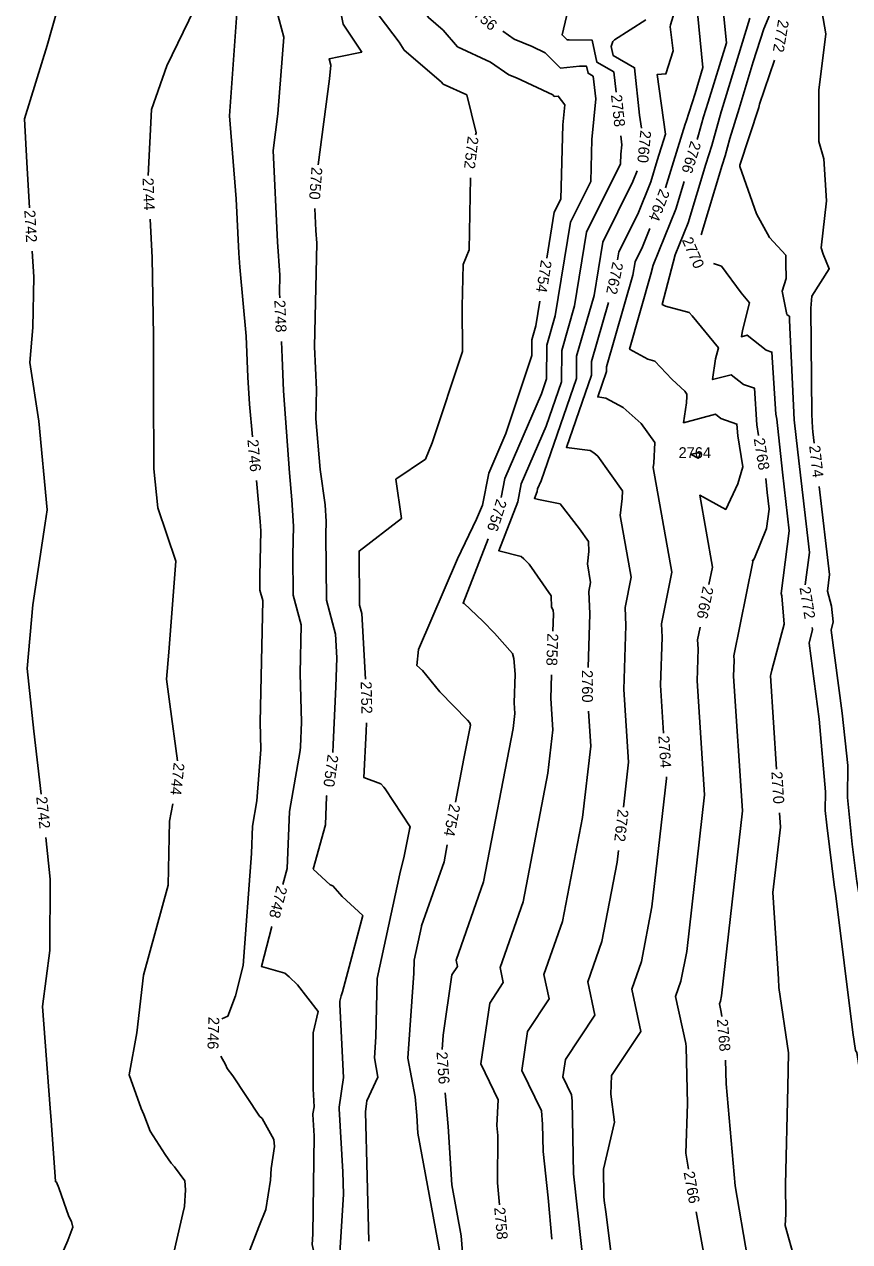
# Model space of a CAD drawing. Extents: x 1326424 to 1329294, y 1001359 to 1003823.
# Drawn here: x 1328128 to 1328279.2, y 1001910 to 1002132.9 of the extents above; entities that cross this region are included whole.
import ezdxf

# ---------------------------------------------------------------- set-up
doc = ezdxf.new("R2010")
doc.units = 0
doc.layers.add('Prop Rem of Exist Asph Pvmt', color=7, linetype='Continuous')
doc.layers.add('Scratch_Level_3', color=7, linetype='Continuous')

msp = doc.modelspace()

# ---------------------------------------------------------------- linework, layer by layer
at = {"layer": 'Prop Rem of Exist Asph Pvmt'}
for points in [[(1328241.88, 1002133.77), (1328236.13, 1002130.1), (1328235.87, 1002129.8), (1328235.55, 1002128.91), (1328235.92, 1002127.24), (1328239.82, 1002125.01), (1328240.76, 1002116.3), (1328241.1, 1002113.91)], [(1328240.33, 1002106.15), (1328239.53, 1002104.16), (1328233.99, 1002093.08), (1328232.41, 1002083.27), (1328229.22, 1002072.21), (1328229.17, 1002068.11), (1328222.69, 1002049.33), (1328222.06, 1002047.86), (1328221.97, 1002047.39), (1328221.48, 1002046.14), (1328222.26, 1002045.95), (1328226.19, 1002045.13), (1328229.74, 1002040.55), (1328231.36, 1002038.22), (1328231.44, 1002036.42), (1328231.19, 1002034.14), (1328231.78, 1002030.76), (1328231.45, 1002029.09), (1328231.66, 1002025.01), (1328231.32, 1002015.14)], [(1328231.37, 1002007.15), (1328231.79, 1002000.78), (1328230.3, 1001987.69), (1328226.62, 1001968.64), (1328223.22, 1001958.93), (1328224.17, 1001954.48), (1328220.22, 1001948.54), (1328219.2, 1001941.39), (1328222.77, 1001934.01), (1328222.99, 1001931.56), (1328223.09, 1001926.51), (1328224.02, 1001918.04), (1328224.69, 1001910.46)]]:
    msp.add_lwpolyline(points, dxfattribs=at)
at = {"layer": 'Scratch_Level_3'}
for points in [[(1328174.09, 1002197.45), (1328174.05, 1002197.26), (1328172.89, 1002195.7), (1328170.57, 1002179.75), (1328170.43, 1002179.18), (1328170.61, 1002178.82), (1328170.68, 1002176.08), (1328170.29, 1002175.71), (1328170.1, 1002175.19), (1328169.74, 1002172.85), (1328164.96, 1002162.58), (1328165.4, 1002155.7), (1328164.24, 1002155.43), (1328161.5, 1002155.85), (1328160.64, 1002149.86), (1328160.24, 1002146.37), (1328159.14, 1002135.67), (1328154.16, 1002125.34), (1328151.31, 1002117.38), (1328150.69, 1002105.26)], [(1328186.52, 1002193.49), (1328185.24, 1002190.14), (1328184.63, 1002189.33), (1328184.32, 1002187.2), (1328182.95, 1002181.36), (1328184.28, 1002178.62), (1328186.74, 1002177.48), (1328183.91, 1002176.94), (1328181.55, 1002174.66), (1328180.02, 1002170.39), (1328179.07, 1002164.22), (1328179.67, 1002160.72), (1328180.72, 1002158.47), (1328179.89, 1002156.68), (1328182.68, 1002146.2), (1328183.84, 1002141.66), (1328185.42, 1002138.19), (1328186.47, 1002132.95), (1328189.85, 1002127.87), (1328185.66, 1002127), (1328183.85, 1002126.65), (1328184.16, 1002125.5), (1328183.96, 1002122.96), (1328181.89, 1002107.19)], [(1328161.06, 1002192.1), (1328159.57, 1002188.92), (1328155.58, 1002182.38), (1328154.2, 1002178.24), (1328153.03, 1002176.74), (1328147.39, 1002166.79), (1328144.91, 1002161.62), (1328140.75, 1002153.04), (1328137.03, 1002143.45), (1328135.1, 1002139.25), (1328132.19, 1002129.06), (1328128.05, 1002115.64), (1328128.5, 1002107.62), (1328128.99, 1002099.36)], [(1328259.04, 1002190.58), (1328258.85, 1002190.19), (1328258.41, 1002185.32), (1328258.53, 1002183.16), (1328258.56, 1002181.96), (1328258.98, 1002175.15), (1328259.79, 1002170.02), (1328260.62, 1002167.82), (1328261.57, 1002164.95), (1328263.57, 1002159.93), (1328265.56, 1002154.79), (1328266.9, 1002151.53), (1328265.77, 1002146.24), (1328265.47, 1002145.5), (1328265.8, 1002144.97), (1328265.97, 1002142.2), (1328264.63, 1002134.73), (1328263.54, 1002132.12), (1328261.58, 1002126.07), (1328258.97, 1002117.54), (1328257.31, 1002112.07), (1328256.4, 1002108.84), (1328255.87, 1002107.16), (1328252.02, 1002094.39)], [(1328229.92, 1002177.59), (1328235.12, 1002172.38), (1328238.26, 1002166.48), (1328239.25, 1002160.72), (1328239.29, 1002158.49), (1328239.55, 1002149.92), (1328241.22, 1002143.6), (1328244.07, 1002140.8), (1328244.85, 1002140.01), (1328245.22, 1002140.03), (1328248.36, 1002140.12), (1328247.82, 1002137.48), (1328246.4, 1002132.83), (1328246.33, 1002132.48), (1328246.92, 1002128.11), (1328245.58, 1002123.88), (1328243.96, 1002123.75), (1328245.51, 1002112.86), (1328243.97, 1002107.99), (1328242.8, 1002104.1), (1328240.41, 1002098.18), (1328236.95, 1002091.26), (1328236.72, 1002089.81)], [(1328176.84, 1002172.32), (1328176.72, 1002171.99), (1328174.72, 1002159), (1328174.75, 1002158.83), (1328174.8, 1002158.72), (1328174.76, 1002158.63), (1328179.34, 1002141.41), (1328179.76, 1002139.78), (1328180.32, 1002138.53), (1328180.99, 1002135.23), (1328174.81, 1002137.15), (1328173.88, 1002136.97), (1328175.6, 1002130.61), (1328174.48, 1002116.58), (1328173.6, 1002109.83), (1328174.39, 1002093.12), (1328174.85, 1002087), (1328174.78, 1002083.72), (1328174.81, 1002082.89)], [(1328199.24, 1002167.33), (1328201.03, 1002160.94), (1328201.9, 1002157.4), (1328204.62, 1002151.23), (1328206.55, 1002145.44), (1328200.31, 1002140.84), (1328197.72, 1002140.5), (1328199.08, 1002138.79), (1328199.71, 1002137.96), (1328202.05, 1002134.19), (1328204.74, 1002131.89), (1328207.39, 1002128.8), (1328213.43, 1002126.04), (1328216.79, 1002123.71), (1328218.2, 1002123.13), (1328224.85, 1002120.01), (1328225.11, 1002119.75), (1328225.86, 1002119.82), (1328227.06, 1002118.23), (1328226.71, 1002114.53), (1328226.32, 1002100.93), (1328225.13, 1002098.55), (1328223.76, 1002090.12)], [(1328276.46, 1002153.66), (1328276.39, 1002153.61), (1328274.88, 1002152.89), (1328274.77, 1002151.74), (1328274.75, 1002151.25), (1328274.22, 1002144.85), (1328274.13, 1002135.42), (1328274.86, 1002131.18), (1328273.56, 1002120.88), (1328273.56, 1002120.81), (1328273.62, 1002113.84), (1328273.62, 1002111.51), (1328274.51, 1002108.33), (1328275.02, 1002100.61), (1328274, 1002092), (1328274.37, 1002090.84), (1328275.51, 1002088.18), (1328272.31, 1002083.2), (1328272.11, 1002080.99), (1328272.32, 1002061.5), (1328272.44, 1002059.04), (1328272.51, 1002058.34), (1328272.75, 1002056.28)], [(1328172.17, 1002148.36), (1328173.66, 1002143.28), (1328169.36, 1002145.31), (1328167.26, 1002144.98), (1328166.99, 1002135.91), (1328167.04, 1002135.73), (1328166.98, 1002134.99), (1328165.64, 1002116.2), (1328166.86, 1002101), (1328167.33, 1002091.06), (1328167.52, 1002088.5), (1328168.68, 1002075.86), (1328168.95, 1002068.36), (1328169.31, 1002063.37), (1328169.85, 1002057.38)], [(1328229.18, 1002142.2), (1328226.55, 1002131.01), (1328227.47, 1002130.09), (1328227.82, 1002130.13), (1328232.06, 1002130.06), (1328232.94, 1002126.01), (1328236.05, 1002124.23), (1328236.45, 1002120.51)], [(1328190.52, 1002137.86), (1328196.71, 1002129.69), (1328197.62, 1002128.23), (1328204.41, 1002122.41), (1328204.77, 1002121.99), (1328209.07, 1002120.02), (1328210.79, 1002113.06), (1328210.71, 1002112.74)], [(1328256.05, 1002135.58), (1328256.65, 1002129.54), (1328253.34, 1002118.69), (1328252.49, 1002116.04), (1328251.55, 1002112.71), (1328251.27, 1002111.83)], [(1328260.95, 1002134.06), (1328255.76, 1002117.08), (1328255.71, 1002116.91), (1328253.97, 1002110.77), (1328252.89, 1002107.37), (1328249.66, 1002096.61), (1328247.29, 1002090.75), (1328245.58, 1002084.21), (1328244.86, 1002081.67), (1328245.49, 1002081.32), (1328249.81, 1002080.15), (1328250.38, 1002079.56), (1328255.19, 1002073.69), (1328254.68, 1002071.71), (1328254.11, 1002067.88), (1328257.54, 1002068.79), (1328259.8, 1002067.01), (1328261.79, 1002066.33), (1328262.22, 1002059.6), (1328262.55, 1002057.65)], [(1328251.35, 1002135.04), (1328252.35, 1002125.02), (1328250.91, 1002120.31), (1328249.27, 1002115.17), (1328249.12, 1002114.64), (1328246.94, 1002107.79), (1328245.51, 1002103.03)], [(1328215.72, 1002131.67), (1328217.79, 1002130.23), (1328221.05, 1002128.89), (1328223.46, 1002127.76), (1328226.29, 1002124.92), (1328229.73, 1002125.28), (1328231.04, 1002125.26), (1328231.31, 1002124), (1328232.27, 1002123.45), (1328232.72, 1002119.32), (1328232.02, 1002111.84), (1328231.79, 1002104.16), (1328228.08, 1002096.73), (1328225.3, 1002079.56), (1328223.76, 1002074.19), (1328223.69, 1002068.01), (1328222.78, 1002065.29), (1328216.09, 1002049.77), (1328215.42, 1002046.3)], [(1328265.45, 1002126.36), (1328262.75, 1002118.3), (1328262.62, 1002117.73), (1328259.12, 1002107.15), (1328259.13, 1002106.89), (1328262.15, 1002098.25), (1328264.54, 1002093.91), (1328267.54, 1002090.69), (1328267.55, 1002089.29), (1328267.58, 1002086.43), (1328266.9, 1002084.08), (1328267.75, 1002079.82), (1328268.14, 1002079.52), (1328268.2, 1002079.5), (1328268.24, 1002078.76), (1328269.08, 1002060.5), (1328269.72, 1002054.63), (1328271.87, 1002036.2), (1328271.11, 1002030.32)], [(1328237.3, 1002112.56), (1328237.48, 1002110.88), (1328237.32, 1002109.15), (1328237.27, 1002107.38), (1328231.04, 1002094.91), (1328228.85, 1002081.42), (1328226.49, 1002073.2), (1328226.42, 1002067.48), (1328223.62, 1002059.35), (1328219.08, 1002048.81), (1328218.43, 1002045.51), (1328214.95, 1002036.55), (1328219.08, 1002035.51), (1328219.55, 1002035.07), (1328220.5, 1002034.09), (1328224.52, 1002028.3), (1328224.62, 1002026.23), (1328224.92, 1002025.69), (1328224.98, 1002024.94), (1328224.87, 1002021.84)], [(1328209.77, 1002104.84), (1328209.52, 1002091.68), (1328208.43, 1002088.94), (1328208.25, 1002081.25), (1328208.3, 1002073.02), (1328202.74, 1002056.29), (1328201.55, 1002053.35), (1328196.09, 1002049.64), (1328197.11, 1002042.45), (1328189.37, 1002036.49), (1328189.46, 1002026.6), (1328189.87, 1002025.07), (1328190.52, 1002013.04)], [(1328248.9, 1002104.19), (1328247.37, 1002099.11), (1328243.23, 1002088.86), (1328242.8, 1002087.22), (1328238.91, 1002073.48), (1328242.28, 1002071.61), (1328243.53, 1002071.27), (1328246.66, 1002067.99), (1328247.5, 1002067.15), (1328249.03, 1002065.79), (1328249.43, 1002065.23), (1328249.38, 1002064.22), (1328249.37, 1002064.2), (1328249.35, 1002063.65), (1328248.81, 1002060), (1328254.63, 1002061.55), (1328255.63, 1002060.76), (1328258.58, 1002059.75), (1328258.72, 1002057.61), (1328259.67, 1002051.93), (1328258.75, 1002048.78), (1328256.54, 1002044.12), (1328251.76, 1002046.71), (1328254.08, 1002033.57), (1328253.43, 1002030.38)], [(1328151.06, 1002097.27), (1328151.46, 1002090.24), (1328151.68, 1002075.93), (1328151.7, 1002066.17), (1328151.76, 1002051.55), (1328152.47, 1002044.4), (1328155.8, 1002034.65), (1328154.49, 1002017.98), (1328154.08, 1002013.02), (1328154.68, 1002008.43), (1328156.1, 1001998.08)], [(1328181.26, 1002099.24), (1328181.46, 1002095.18), (1328181.63, 1002092.86), (1328181.2, 1002073.9), (1328181.54, 1002066.05), (1328181.44, 1002060.72), (1328182.21, 1002051.4), (1328183.12, 1002044.98), (1328183.31, 1002041.89), (1328183.25, 1002039.53), (1328183.36, 1002027.52), (1328185.05, 1002021.27), (1328185.29, 1002016.93), (1328185.07, 1002011.61), (1328184.6, 1002001.05), (1328184.52, 1001999.61)], [(1328242.64, 1002095.57), (1328241.29, 1002092.21), (1328239.91, 1002089.44), (1328239.51, 1002086.99), (1328234.68, 1002070.23), (1328234.67, 1002069.36), (1328233.07, 1002064.71), (1328234.59, 1002064.51), (1328237.77, 1002062.76), (1328241.05, 1002059.84), (1328243.54, 1002056.38), (1328243.35, 1002052.59), (1328243.26, 1002051.82), (1328246.64, 1002032.63), (1328244.74, 1002023.19), (1328244.87, 1002020.74), (1328244.57, 1002011.93), (1328245.15, 1002003.14)], [(1328129.47, 1002091.38), (1328129.74, 1002086.73), (1328129.59, 1002077.41), (1328129.06, 1002071.01), (1328130.67, 1002060.25), (1328132.22, 1002044.06), (1328131.85, 1002041.62), (1328129.6, 1002026.67), (1328128.55, 1002014.97), (1328129.75, 1002003.49), (1328131.13, 1001991.99)], [(1328254.31, 1002089.18), (1328255.73, 1002088.67), (1328259.37, 1002083.79), (1328260.89, 1002081.94), (1328259.59, 1002076.91), (1328259.42, 1002075.75), (1328260.46, 1002076.03), (1328263.97, 1002073.26), (1328264.99, 1002072.92), (1328265.72, 1002061.58), (1328265.88, 1002060.62), (1328266.93, 1002050.93), (1328268.18, 1002040.19), (1328266.69, 1002028.71), (1328266.8, 1002028.32), (1328267.23, 1002023.11), (1328265, 1002014.71), (1328264.77, 1002013.86), (1328264.73, 1002013.63), (1328265.86, 1001996.55)], [(1328222.48, 1002082.23), (1328221.75, 1002077.71), (1328221.02, 1002075.18), (1328220.99, 1002072.28), (1328216.25, 1002058.03), (1328213.11, 1002050.73), (1328211.97, 1002044.88), (1328210.86, 1002042.34), (1328207.42, 1002035.07), (1328200.22, 1002018.44), (1328199.94, 1002015.56), (1328200.98, 1002014.6), (1328204.13, 1002010.71), (1328209.21, 1002005.53), (1328209.65, 1002005.03), (1328209.77, 1002004.63), (1328208.57, 1001998.5), (1328207.03, 1001990.52)], [(1328235.06, 1002082), (1328231.95, 1002071.22), (1328231.92, 1002068.73), (1328227.34, 1002055.46), (1328231.68, 1002054.89), (1328232.37, 1002054.51), (1328233.07, 1002053.88), (1328237.65, 1002047.52), (1328237.58, 1002046.13), (1328237.22, 1002042.98), (1328239.21, 1002031.69), (1328238.09, 1002026.14), (1328238.26, 1002022.88), (1328237.87, 1002011.12), (1328238.74, 1001997.82), (1328237.81, 1001989.61)], [(1328175.15, 1002074.89), (1328175.28, 1002071.92), (1328175.5, 1002065.82), (1328176.59, 1002050.82), (1328177.03, 1002045.87), (1328177.33, 1002041.04), (1328177.2, 1002035.75), (1328177.27, 1002028.44), (1328178.75, 1002022.99), (1328178.55, 1002014.06), (1328178.81, 1002005.16), (1328178.61, 1002000.66), (1328178.57, 1001999.97), (1328176.61, 1001988.82), (1328176.19, 1001978.36), (1328175.4, 1001975.46)], [(1328251.46, 1002054.51), (1328250.24, 1002054.21), (1328250.18, 1002054.2), (1328251.51, 1002053.48), (1328251.65, 1002053.76), (1328251.83, 1002054.38), (1328251.46, 1002054.51)], [(1328170.56, 1002049.41), (1328171.24, 1002041.89), (1328171.35, 1002040.18), (1328171.15, 1002031.97), (1328171.18, 1002029.36), (1328171.71, 1002027.41), (1328171.22, 1002005.16), (1328171.36, 1002000.18), (1328170.64, 1001990.76), (1328169.82, 1001986.1), (1328169.62, 1001981.13), (1328168.15, 1001960.58), (1328166.73, 1001955.06), (1328165.29, 1001951.3), (1328164.23, 1001950.81)], [(1328263.86, 1002049.75), (1328264.14, 1002047.23), (1328264.49, 1002044.18), (1328264.03, 1002040.6), (1328261.78, 1002035.22), (1328261.57, 1002034.77), (1328261.45, 1002034.84), (1328261.51, 1002034.5), (1328258.03, 1002017.28), (1328258.08, 1002016.48), (1328257.98, 1002013.56), (1328259.61, 1001988.92), (1328255.74, 1001955.03), (1328255.56, 1001954.07), (1328255.39, 1001953.58), (1328255.71, 1001952.07), (1328255.8, 1001951.24)], [(1328273.68, 1002048.34), (1328275.57, 1002032.21), (1328275.17, 1002029.17), (1328275.91, 1002026.39), (1328276.23, 1002023.51), (1328275.86, 1002022), (1328277.89, 1002006.78), (1328278.91, 1001997.2), (1328278.85, 1001991.36), (1328279.7, 1001982.81), (1328280.56, 1001975.97), (1328281.23, 1001972.09), (1328282.01, 1001965.89), (1328284.21, 1001949.16)], [(1328212.99, 1002038.71), (1328208.41, 1002026.95), (1328208.62, 1002026.9), (1328212.04, 1002023.67), (1328214.18, 1002021.47), (1328217.45, 1002017.73), (1328217.72, 1002016.84), (1328217.93, 1002013.97), (1328217.75, 1002008.68), (1328217.88, 1002006.72), (1328217.58, 1002004.01), (1328212.15, 1001975.92), (1328207.13, 1001961.6), (1328207.38, 1001960.43), (1328206.35, 1001958.87), (1328204.77, 1001947.87), (1328204.58, 1001945.21)], [(1328251.85, 1002022.54), (1328251.39, 1002020.24), (1328251.47, 1002018.61), (1328251.27, 1002012.75), (1328252.65, 1001991.88), (1328249.38, 1001963.19), (1328248.32, 1001957.71), (1328247.34, 1001954.92), (1328249.2, 1001946.29), (1328249.26, 1001945.73), (1328249.52, 1001935.26), (1328249.25, 1001926.23), (1328249.44, 1001924.77), (1328249.7, 1001923.33)], [(1328272.39, 1002022.51), (1328272.42, 1002022.11), (1328271.82, 1002019.65), (1328273.68, 1002005.68), (1328274.8, 1001992.42), (1328274.77, 1001988.98), (1328275.04, 1001986.28), (1328276.47, 1001974.9), (1328276.65, 1001973.83), (1328279.85, 1001948.31), (1328280.28, 1001945.05), (1328280.53, 1001944.64), (1328282.71, 1001930.87), (1328282.88, 1001923.35)], [(1328224.6, 1002013.85), (1328224.46, 1002009.5), (1328224.84, 1002003.75), (1328223.94, 1001995.85), (1328219.39, 1001972.28), (1328215.18, 1001960.26), (1328215.78, 1001957.46), (1328213.29, 1001953.7), (1328211.69, 1001942.58), (1328214.87, 1001936.01), (1328214.62, 1001931.29), (1328214.78, 1001929.48), (1328214.71, 1001920.79), (1328215.07, 1001916.76)], [(1328190.72, 1002005.05), (1328190.65, 1002003.46), (1328190.2, 1001995.04), (1328193.34, 1001993.88), (1328193.91, 1001993.24), (1328194.12, 1001992.94), (1328198.72, 1001985.99), (1328198.62, 1001985.54), (1328198.61, 1001985.52), (1328197.62, 1001980.6), (1328196.81, 1001977.36), (1328192.65, 1001958.19), (1328192.43, 1001947.51), (1328192.17, 1001943.67), (1328192.81, 1001940.15), (1328190.75, 1001935.79), (1328190.7, 1001935.31), (1328190.55, 1001933.78), (1328191.14, 1001910.13)], [(1328245.68, 1001995.16), (1328245.7, 1001994.85), (1328243.02, 1001971.36), (1328241.09, 1001961.35), (1328239.3, 1001956.25), (1328240.96, 1001948.53), (1328235.58, 1001940.44), (1328235.48, 1001937.06), (1328236.16, 1001931.91), (1328234.11, 1001923.31), (1328234.2, 1001918.36), (1328234.29, 1001917.54), (1328234.55, 1001915.49), (1328236.75, 1001898.05)], [(1328183.42, 1001991.7), (1328183.4, 1001991.54), (1328183.19, 1001986.38), (1328180.96, 1001978.22), (1328184.05, 1001975.39), (1328184.54, 1001975.18), (1328186.23, 1001973.25), (1328190.02, 1001969.75), (1328186.31, 1001955.8), (1328186.08, 1001955.02), (1328185.85, 1001954.08), (1328185.85, 1001953.48), (1328186.52, 1001940.09), (1328185.71, 1001934.68), (1328185.71, 1001934.37), (1328186.4, 1001922.79), (1328186.5, 1001918.72), (1328185.86, 1001907.89), (1328188.31, 1001896.91)], [(1328155.23, 1001990.21), (1328154.6, 1001987.02), (1328154.35, 1001975.32), (1328149.89, 1001958.8), (1328148.61, 1001948.25), (1328147.22, 1001940.6), (1328149.43, 1001934.44), (1328149.94, 1001933.31), (1328151.1, 1001930.24), (1328153.85, 1001925.97), (1328154.93, 1001924.39), (1328155.57, 1001923.75), (1328157.44, 1001921.19), (1328157.54, 1001919.51), (1328157.4, 1001916.47), (1328157.05, 1001915.21), (1328154.39, 1001903.52), (1328153.63, 1001898.94), (1328153.3, 1001897.95), (1328153.18, 1001894.26)], [(1328266.39, 1001988.57), (1328266.56, 1001985.95), (1328265.19, 1001973.96), (1328266.21, 1001958.16), (1328266.25, 1001956.58), (1328268.05, 1001944.6), (1328267.89, 1001938.34), (1328267.49, 1001920.48), (1328267.52, 1001915.06), (1328267.44, 1001912.99), (1328270.95, 1001900.29), (1328272.81, 1001895.72), (1328274.5, 1001889.91)], [(1328131.98, 1001984.04), (1328132.78, 1001976.4), (1328132.67, 1001963.36), (1328131.37, 1001953.08), (1328132.76, 1001934.46), (1328132.95, 1001932.22), (1328133.72, 1001921.03), (1328133.94, 1001920.94), (1328134.34, 1001919.9), (1328136.19, 1001914.65), (1328136.68, 1001913.73), (1328136.89, 1001912.67), (1328136.01, 1001910.21), (1328134.17, 1001906.03), (1328133.24, 1001896.68), (1328132.44, 1001887.75), (1328131.89, 1001885.62)], [(1328205.52, 1001982.67), (1328204.92, 1001979.57), (1328200.81, 1001967.85), (1328200.78, 1001967.73), (1328199.45, 1001961.58), (1328199.4, 1001959.2), (1328198.32, 1001943.6), (1328199.62, 1001936.53), (1328199.93, 1001933.15), (1328200.12, 1001929.9), (1328204.4, 1001906.75), (1328204.83, 1001901.14), (1328206.87, 1001885.6), (1328206.95, 1001885.01), (1328207.05, 1001884.3)], [(1328236.9, 1001981.66), (1328236.66, 1001979.52), (1328233.85, 1001964.99), (1328231.26, 1001957.59), (1328232.57, 1001951.51), (1328227.16, 1001943.37), (1328226.71, 1001940.2), (1328228.29, 1001936.93), (1328228.39, 1001935.84), (1328228.64, 1001922.43), (1328230.11, 1001909.13), (1328230.17, 1001908.61), (1328231.09, 1001901.31), (1328232.13, 1001891.33), (1328232.41, 1001887.59), (1328232.68, 1001884.78)], [(1328173.37, 1001967.73), (1328171.46, 1001960.43), (1328175.76, 1001959.21), (1328176.55, 1001958.54), (1328178.08, 1001957.04), (1328181.89, 1001952.17), (1328180.95, 1001948.29), (1328180.94, 1001938.02), (1328181.1, 1001934.74), (1328180.9, 1001933.41), (1328180.91, 1001933.34), (1328181.14, 1001929.41), (1328180.89, 1001911.41), (1328180.77, 1001909.5), (1328181.27, 1001907.28), (1328182.17, 1001882.71), (1328182.15, 1001882.64), (1328182.17, 1001882.56), (1328182.17, 1001882.51), (1328183.48, 1001873.86)], [(1328164.01, 1001944), (1328164.86, 1001942.48), (1328165.22, 1001941.72), (1328166.25, 1001940.37), (1328171.13, 1001933.01), (1328171.6, 1001932.57), (1328173.71, 1001928.76), (1328173.84, 1001927.48), (1328173.23, 1001923.44), (1328173.15, 1001921.26), (1328172.25, 1001915.92), (1328171.01, 1001912.75), (1328169.01, 1001907.66), (1328167.39, 1001900.03), (1328166.98, 1001895.4), (1328166.01, 1001890.85), (1328168.75, 1001884.65), (1328168.87, 1001882.65), (1328168.64, 1001882.02), (1328169.26, 1001871.44), (1328169.13, 1001866.98), (1328169.57, 1001860.85), (1328171.86, 1001848.78)], [(1328256.51, 1001943.27), (1328256.62, 1001938.92), (1328258.24, 1001920.25), (1328260.54, 1001907.05), (1328262.68, 1001899.33), (1328268.03, 1001886.16), (1328269.74, 1001880.27), (1328276.76, 1001865.11), (1328278.3, 1001861.57), (1328279.69, 1001858.71), (1328279.07, 1001857.02), (1328281.43, 1001847.71)], [(1328205.15, 1001937.26), (1328205.71, 1001931.13), (1328206.37, 1001920.43), (1328208.09, 1001911.1), (1328209.54, 1001892.6), (1328210.54, 1001884.92), (1328210.82, 1001882.95), (1328212.42, 1001870.72), (1328214.82, 1001853.41), (1328215.31, 1001850.31), (1328217.12, 1001838.16), (1328217.14, 1001838.05)], [(1328251.12, 1001915.46), (1328253.96, 1001899.75), (1328253.86, 1001899.21), (1328254.03, 1001897.86), (1328260.51, 1001879.12), (1328260.56, 1001878.28), (1328260.15, 1001874.93), (1328262.83, 1001864.75), (1328262.84, 1001839.23), (1328262.75, 1001838.53), (1328271.02, 1001822.16), (1328272.23, 1001819.99), (1328272.48, 1001819.55)]]:
    msp.add_lwpolyline(points, dxfattribs=at)

# ---------------------------------------------------------------- texts
at = {"layer": 'Prop Rem of Exist Asph Pvmt'}
for rotation, p in [(264.3164, (1328240.91, 1002113.6)), (270.3343, (1328230.17, 1002014.7))]:
    msp.add_text('2760', height=2, rotation=rotation, dxfattribs=at).set_placement(p)
at = {"layer": 'Scratch_Level_3'}
for s, rotation, p in [('2756', 318.8406, (1328209.08, 1002135.56)), ('2772', 260.3496, (1328266.16, 1002133.89)), ('2758', 276.1326, (1328235.5, 1002119.99)), ('2752', 263.231, (1328209.28, 1002112.52)), ('2766', 252.7704, (1328250.16, 1002111.72)), ('2750', 265.4675, (1328180.66, 1002106.87)), ('2744', 272.6812, (1328149.68, 1002104.8)), ('2764', 248.9851, (1328244.49, 1002102.96)), ('2742', 273.3948, (1328128.02, 1002098.89)), ('2770', 293.6688, (1328248.46, 1002093.46)), ('2754', 260.8068, (1328222.71, 1002089.87)), ('2762', 258.0123, (1328235.84, 1002089.56)), ('2748', 272.4504, (1328173.83, 1002082.43)), ('2768', 279.4778, (1328261.64, 1002057.05)), ('2746', 275.1397, (1328168.89, 1002056.87)), ('2774', 276.6665, (1328271.81, 1002055.75)), ('2756', 252.2284, (1328214.58, 1002046.15)), ('2766', 258.5988, (1328252.37, 1002030.15)), ('2772', 279.2859, (1328270.04, 1002029.8)), ('2758', 268.0748, (1328223.86, 1002021.46)), ('2752', 271.4019, (1328189.65, 1002012.61)), ('2764', 273.7796, (1328244.18, 1002002.64)), ('2750', 262.1372, (1328183.62, 1001999.33)), ('2744', 263.7042, (1328155.41, 1001997.81)), ('2770', 273.7796, (1328264.89, 1001996.07)), ('2742', 276.09, (1328130.19, 1001991.47)), ('2754', 259.0725, (1328205.97, 1001990.3)), ('2762', 263.4959, (1328236.77, 1001989.29)), ('2748', 255.2752, (1328174.33, 1001975.32)), ('2746', 268.1406, (1328161.77, 1001951.22)), ('2768', 275.132, (1328254.9, 1001950.72)), ('2756', 274.0999, (1328203.54, 1001944.75)), ('2766', 280.2214, (1328248.8, 1001922.73)), ('2758', 275.0897, (1328214.11, 1001916.25))]:
    msp.add_text(s, height=2, rotation=rotation, dxfattribs=at).set_placement(p)
msp.add_text('2764', height=2, dxfattribs=at).set_placement((1328247.89, 1002053.51))

doc.saveas('drawing.dxf')
